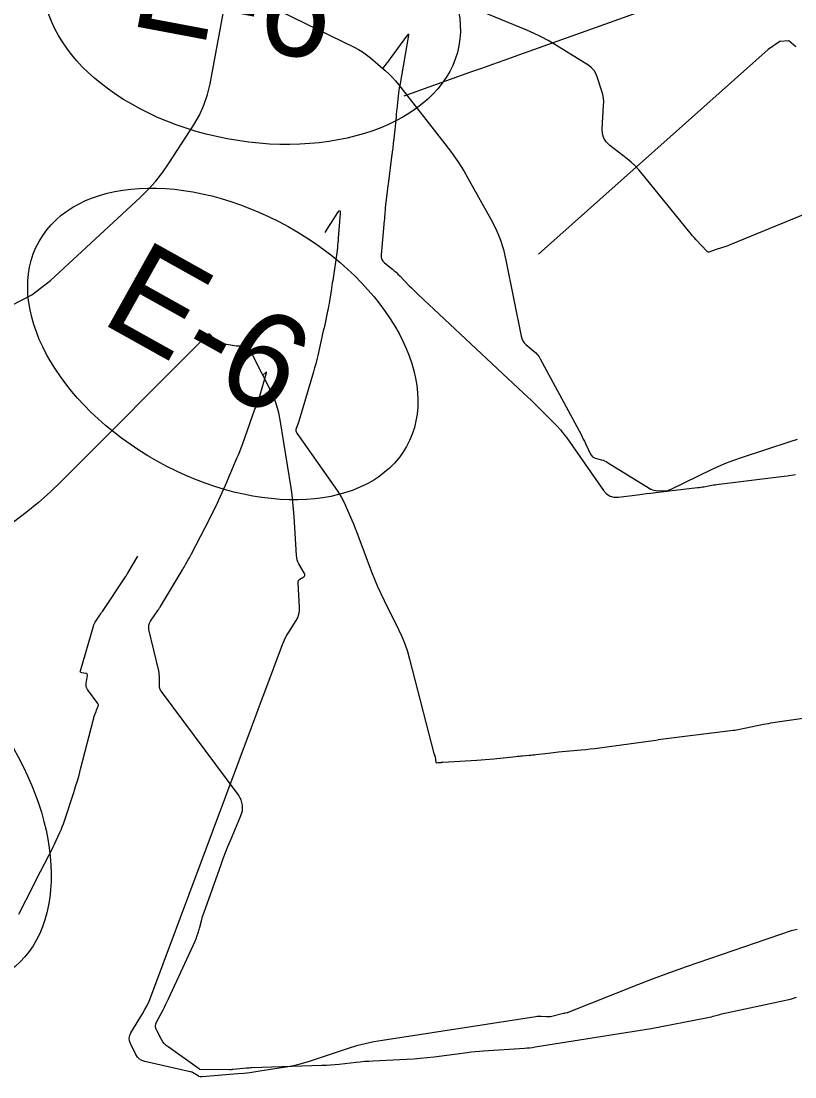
# Model space of a CAD drawing. Extents: x 1005228 to 1008882, y 1883389 to 1885754.
# Drawn here: x 1008004.6 to 1008055, y 1884412.1 to 1884480.9 of the extents above; entities that cross this region are included whole.
import ezdxf

# ---------------------------------------------------------------- set-up
doc = ezdxf.new("R2010")
doc.units = 0
for name, color, linetype in [('ATDIMS', 7, 'Continuous'), ('C-ANNO-NOTE', 7, 'Continuous'), ('R_Erosion', 7, 'Continuous'), ('TSOBSTACLE', 7, 'Continuous')]:
    doc.layers.add(name, color=color, linetype=linetype)

msp = doc.modelspace()

# ---------------------------------------------------------------- linework, layer by layer
at = {"layer": 'ATDIMS'}
for points in [[(1008024.395, 1884467.109), (1008024.638, 1884467.493), (1008024.679, 1884467.557), (1008024.719, 1884467.621), (1008024.76, 1884467.685), (1008024.8, 1884467.749), (1008025.223, 1884468.415), (1008025.295, 1884468.511), (1008025.343, 1884468.535), (1008025.367, 1884468.487), (1008025.367, 1884468.367), (1008025.245, 1884466.744), (1008025.24, 1884466.676), (1008025.234, 1884466.609), (1008025.229, 1884466.542), (1008025.222, 1884466.475), (1008025.198, 1884466.206), (1008025.191, 1884466.139), (1008025.184, 1884466.072), (1008025.175, 1884466.005), (1008025.166, 1884465.938), (1008024.883, 1884463.986), (1008024.858, 1884463.818), (1008024.832, 1884463.65), (1008024.806, 1884463.482), (1008024.78, 1884463.314), (1008024.672, 1884462.642), (1008024.644, 1884462.475), (1008024.614, 1884462.307), (1008024.582, 1884462.141), (1008024.547, 1884461.974), (1008024.36, 1884461.102), (1008024.317, 1884460.901), (1008024.272, 1884460.701), (1008024.228, 1884460.5), (1008024.182, 1884460.3), (1008023.907, 1884459.096), (1008023.844, 1884458.829), (1008023.776, 1884458.563), (1008023.705, 1884458.299), (1008023.629, 1884458.035), (1008022.765, 1884455.11), (1008022.758, 1884455.084), (1008022.75, 1884455.058), (1008022.743, 1884455.032), (1008022.735, 1884455.007), (1008022.706, 1884454.904), (1008022.698, 1884454.878), (1008022.69, 1884454.852), (1008022.681, 1884454.827), (1008022.672, 1884454.802), (1008022.508, 1884454.353), (1008022.488, 1884454.271), (1008022.488, 1884454.192), (1008022.508, 1884454.115), (1008022.549, 1884454.041), (1008025.174, 1884450.298), (1008025.322, 1884450.075), (1008025.458, 1884449.845), (1008025.583, 1884449.609), (1008025.695, 1884449.367), (1008026.122, 1884448.383), (1008026.228, 1884448.136), (1008026.33, 1884447.889), (1008026.429, 1884447.639), (1008026.525, 1884447.389), (1008027.417, 1884445.012), (1008027.603, 1884444.535), (1008027.802, 1884444.063), (1008028.012, 1884443.596), (1008028.234, 1884443.134), (1008029.162, 1884441.267), (1008029.38, 1884440.798), (1008029.573, 1884440.32), (1008029.741, 1884439.832), (1008029.883, 1884439.335), (1008031.47, 1884433.19), (1008031.476, 1884433.169), (1008031.482, 1884433.148), (1008031.489, 1884433.127), (1008031.497, 1884433.107), (1008031.528, 1884433.025), (1008031.535, 1884433.004), (1008031.541, 1884432.984), (1008031.546, 1884432.962), (1008031.55, 1884432.941), (1008031.596, 1884432.626), (1008031.602, 1884432.608), (1008031.612, 1884432.595), (1008031.627, 1884432.588), (1008031.646, 1884432.586), (1008031.732, 1884432.59), (1008031.754, 1884432.591), (1008031.776, 1884432.593), (1008031.797, 1884432.594), (1008031.819, 1884432.596), (1008031.943, 1884432.608), (1008031.97, 1884432.61), (1008031.998, 1884432.613), (1008032.026, 1884432.615), (1008032.054, 1884432.616), (1008034.265, 1884432.753), (1008034.541, 1884432.771), (1008034.817, 1884432.793), (1008035.093, 1884432.817), (1008035.369, 1884432.845), (1008036.806, 1884432.996), (1008036.914, 1884433.007), (1008037.022, 1884433.017), (1008037.131, 1884433.027), (1008037.239, 1884433.036), (1008037.672, 1884433.071), (1008037.781, 1884433.08), (1008037.889, 1884433.091), (1008037.997, 1884433.102), (1008038.105, 1884433.115), (1008038.905, 1884433.211), (1008039.074, 1884433.231), (1008039.244, 1884433.25), (1008039.413, 1884433.267), (1008039.583, 1884433.283), (1008041.049, 1884433.416), (1008041.35, 1884433.445), (1008041.651, 1884433.478), (1008041.951, 1884433.514), (1008042.25, 1884433.553), (1008046.075, 1884434.078)], [(1008057.004, 1884435.683), (1008053.526, 1884435.172), (1008053.377, 1884435.149), (1008053.227, 1884435.124), (1008053.079, 1884435.096), (1008052.93, 1884435.067), (1008051.381, 1884434.744), (1008051.271, 1884434.722), (1008051.161, 1884434.703), (1008051.05, 1884434.686), (1008050.939, 1884434.671), (1008046.075, 1884434.078)]]:
    msp.add_lwpolyline(points, dxfattribs=at)
at = {"layer": 'C-ANNO-NOTE'}
for points in [[(1008003.991, 1884462.374), (1008005.303, 1884463.038), (1008006.51, 1884463.973), (1008012.358, 1884469.391), (1008012.881, 1884469.906), (1008013.368, 1884470.451), (1008013.821, 1884471.025), (1008014.238, 1884471.629), (1008015.836, 1884474.104), (1008016.202, 1884474.736), (1008016.503, 1884475.394), (1008016.737, 1884476.079), (1008016.906, 1884476.79), (1008017.871, 1884481.95)], [(1008021.499, 1884481.502), (1008026.278, 1884479.172), (1008026.559, 1884479.024), (1008026.828, 1884478.859), (1008027.086, 1884478.677), (1008027.332, 1884478.478), (1008028.297, 1884477.649), (1008028.532, 1884477.436), (1008028.756, 1884477.213), (1008028.969, 1884476.978), (1008029.171, 1884476.733), (1008032.18, 1884472.884), (1008032.613, 1884472.308), (1008033.022, 1884471.717), (1008033.409, 1884471.11), (1008033.772, 1884470.489), (1008035.179, 1884467.971), (1008035.504, 1884467.332), (1008035.777, 1884466.673), (1008035.996, 1884465.995), (1008036.162, 1884465.297), (1008037.139, 1884460.348), (1008037.184, 1884460.192), (1008037.253, 1884460.049), (1008037.345, 1884459.921), (1008037.463, 1884459.807), (1008037.98, 1884459.382), (1008038.103, 1884459.271), (1008038.213, 1884459.149), (1008038.311, 1884459.017), (1008038.397, 1884458.875), (1008041.045, 1884453.944), (1008041.121, 1884453.8), (1008041.196, 1884453.654), (1008041.269, 1884453.508), (1008041.34, 1884453.361), (1008041.669, 1884452.668), (1008041.722, 1884452.58), (1008041.79, 1884452.509), (1008041.871, 1884452.456), (1008041.967, 1884452.419), (1008042.379, 1884452.309), (1008042.481, 1884452.277), (1008042.579, 1884452.239), (1008042.675, 1884452.193), (1008042.767, 1884452.14), (1008045.474, 1884450.449), (1008045.582, 1884450.39), (1008045.695, 1884450.347), (1008045.812, 1884450.319), (1008045.934, 1884450.307), (1008046.432, 1884450.287), (1008046.555, 1884450.289), (1008046.675, 1884450.306), (1008046.791, 1884450.339), (1008046.905, 1884450.386), (1008049.54, 1884451.67), (1008050.02, 1884451.894), (1008050.506, 1884452.101), (1008051, 1884452.291), (1008051.5, 1884452.465), (1008054.653, 1884453.497), (1008055.146, 1884453.659)], [(1008055.106, 1884421.728), (1008054.914, 1884421.688), (1008054.724, 1884421.631), (1008047.892, 1884419.293), (1008047.112, 1884419.021), (1008046.336, 1884418.739), (1008045.564, 1884418.448), (1008044.795, 1884418.147), (1008040.245, 1884416.335), (1008040.218, 1884416.325), (1008040.191, 1884416.316), (1008040.163, 1884416.308), (1008040.135, 1884416.301), (1008040.022, 1884416.274), (1008039.994, 1884416.267), (1008039.965, 1884416.26), (1008039.937, 1884416.254), (1008039.909, 1884416.247), (1008039.135, 1884416.06), (1008039.05, 1884416.043), (1008038.965, 1884416.033), (1008038.88, 1884416.03), (1008038.794, 1884416.033), (1008038.449, 1884416.059), (1008038.363, 1884416.064), (1008038.277, 1884416.063), (1008038.191, 1884416.057), (1008038.106, 1884416.046), (1008028.118, 1884414.507), (1008027.552, 1884414.408), (1008026.991, 1884414.286), (1008026.436, 1884414.14), (1008025.886, 1884413.971), (1008023.354, 1884413.136), (1008022.977, 1884413.02), (1008022.597, 1884412.919), (1008022.214, 1884412.834), (1008021.826, 1884412.764), (1008020.269, 1884412.514), (1008019.879, 1884412.455), (1008019.489, 1884412.403), (1008019.097, 1884412.359), (1008018.705, 1884412.323), (1008016.387, 1884412.13), (1008016.315, 1884412.129), (1008016.245, 1884412.14), (1008016.178, 1884412.162), (1008016.114, 1884412.195), (1008015.759, 1884412.415), (1008015.747, 1884412.421), (1008015.735, 1884412.427), (1008015.723, 1884412.432), (1008015.71, 1884412.435), (1008015.658, 1884412.449), (1008015.645, 1884412.452), (1008015.632, 1884412.455), (1008015.619, 1884412.458), (1008015.606, 1884412.461), (1008012.648, 1884413.135), (1008012.466, 1884413.197), (1008012.311, 1884413.291), (1008012.181, 1884413.42), (1008012.078, 1884413.581), (1008011.719, 1884414.296), (1008011.653, 1884414.473), (1008011.636, 1884414.649), (1008011.667, 1884414.823), (1008011.747, 1884414.995), (1008012.503, 1884416.241), (1008012.657, 1884416.508), (1008012.799, 1884416.782), (1008012.927, 1884417.063), (1008013.042, 1884417.35), (1008019.598, 1884434.88), (1008019.816, 1884435.462), (1008020.034, 1884436.043), (1008020.251, 1884436.625), (1008020.469, 1884437.206), (1008021.619, 1884440.27), (1008021.703, 1884440.48), (1008021.798, 1884440.684), (1008021.904, 1884440.884), (1008022.02, 1884441.078), (1008022.504, 1884441.844), (1008022.608, 1884442.04), (1008022.679, 1884442.244), (1008022.716, 1884442.458), (1008022.72, 1884442.68), (1008022.625, 1884444.305), (1008022.629, 1884444.375), (1008022.65, 1884444.437), (1008022.687, 1884444.489), (1008022.742, 1884444.533), (1008022.994, 1884444.691), (1008023.045, 1884444.734), (1008023.07, 1884444.783), (1008023.071, 1884444.838), (1008023.046, 1884444.899), (1008022.684, 1884445.531), (1008022.619, 1884445.661), (1008022.57, 1884445.795), (1008022.538, 1884445.934), (1008022.521, 1884446.077), (1008022.373, 1884448.613), (1008022.339, 1884449.083), (1008022.294, 1884449.553), (1008022.238, 1884450.021), (1008022.17, 1884450.488), (1008021.469, 1884454.905), (1008021.377, 1884455.371), (1008021.25, 1884455.826), (1008021.087, 1884456.269), (1008020.89, 1884456.702), (1008019.659, 1884459.147), (1008019.632, 1884459.206), (1008019.608, 1884459.265), (1008019.588, 1884459.326), (1008019.57, 1884459.387), (1008019.508, 1884459.637), (1008019.486, 1884459.691), (1008019.453, 1884459.727), (1008019.407, 1884459.746), (1008019.349, 1884459.748), (1008018.956, 1884459.703), (1008018.869, 1884459.696), (1008018.783, 1884459.695), (1008018.696, 1884459.7), (1008018.61, 1884459.71), (1008017.446, 1884459.889), (1008017.358, 1884459.911), (1008017.281, 1884459.951), (1008017.215, 1884460.007), (1008017.161, 1884460.08), (1008016.964, 1884460.404), (1008016.913, 1884460.467), (1008016.857, 1884460.492), (1008016.797, 1884460.481), (1008016.732, 1884460.432), (1008007.232, 1884450.916), (1008006.492, 1884450.203), (1008005.726, 1884449.521), (1008004.933, 1884448.87), (1008004.113, 1884448.25)]]:
    msp.add_lwpolyline(points, dxfattribs=at)
at = {"layer": 'R_Erosion'}
for centre, major_axis in [((1008019.637, 1884481.8), (13.46, -2.537)), ((1008017.727, 1884459.846), (11.958, -6.679)), ((1007995.859, 1884430.167), (7.993, -11.124))]:
    msp.add_ellipse(centre, major_axis=major_axis, ratio=0.638788, dxfattribs=at)
at = {"layer": 'TSOBSTACLE'}
for points in [[(1008053.568, 1884484.601), (1008036.738, 1884478.567), (1008036.016, 1884478.308), (1008035.293, 1884478.049), (1008034.571, 1884477.791), (1008033.848, 1884477.534), (1008029.511, 1884475.989)], [(1008056.82, 1884468.807), (1008050.798, 1884466.314), (1008050.699, 1884466.274), (1008050.599, 1884466.237), (1008050.498, 1884466.202), (1008050.396, 1884466.169), (1008049.898, 1884466.017), (1008049.84, 1884465.998), (1008049.782, 1884465.979), (1008049.725, 1884465.958), (1008049.668, 1884465.936), (1008049.441, 1884465.845), (1008049.386, 1884465.831), (1008049.335, 1884465.833), (1008049.287, 1884465.852), (1008049.244, 1884465.889), (1008048.546, 1884466.633), (1008048.417, 1884466.773), (1008048.29, 1884466.915), (1008048.167, 1884467.06), (1008048.046, 1884467.206), (1008045.036, 1884470.93), (1008044.81, 1884471.194), (1008044.569, 1884471.444), (1008044.314, 1884471.68), (1008044.046, 1884471.901), (1008042.918, 1884472.777), (1008042.69, 1884472.997), (1008042.533, 1884473.25), (1008042.446, 1884473.535), (1008042.43, 1884473.852), (1008042.517, 1884475.365), (1008042.52, 1884475.607), (1008042.501, 1884475.846), (1008042.461, 1884476.082), (1008042.399, 1884476.315), (1008042.106, 1884477.244), (1008042.016, 1884477.463), (1008041.893, 1884477.657), (1008041.736, 1884477.824), (1008041.546, 1884477.966), (1008039.345, 1884479.333), (1008038.905, 1884479.595), (1008038.455, 1884479.838), (1008037.995, 1884480.062), (1008037.526, 1884480.268), (1008032.82, 1884482.216)], [(1008028.119, 1884477.728), (1008028.432, 1884478.144), (1008028.484, 1884478.213), (1008028.536, 1884478.283), (1008028.587, 1884478.352), (1008028.639, 1884478.422), (1008029.78, 1884479.972), (1008029.784, 1884479.979), (1008029.789, 1884479.986), (1008029.793, 1884479.993), (1008029.796, 1884480), (1008029.809, 1884480.031), (1008029.812, 1884480.037), (1008029.815, 1884480.038), (1008029.816, 1884480.036), (1008029.817, 1884480.03), (1008029.82, 1884479.986), (1008029.82, 1884479.979), (1008029.82, 1884479.973), (1008029.815, 1884479.946), (1008029.245, 1884476.685), (1008029.217, 1884476.516), (1008029.192, 1884476.346), (1008029.169, 1884476.176), (1008029.149, 1884476.005), (1008029.076, 1884475.322), (1008029.057, 1884475.152), (1008029.039, 1884474.981), (1008029.021, 1884474.81), (1008029.004, 1884474.639), (1008028.857, 1884473.209), (1008028.825, 1884472.914), (1008028.792, 1884472.619), (1008028.757, 1884472.324), (1008028.719, 1884472.03), (1008028.51, 1884470.432), (1008028.49, 1884470.274), (1008028.469, 1884470.116), (1008028.449, 1884469.958), (1008028.43, 1884469.8), (1008028.336, 1884469.046), (1008028.325, 1884468.949), (1008028.314, 1884468.852), (1008028.305, 1884468.755), (1008028.297, 1884468.658), (1008028.268, 1884468.269), (1008028.26, 1884468.171), (1008028.253, 1884468.074), (1008028.244, 1884467.977), (1008028.236, 1884467.88), (1008028.031, 1884465.646), (1008028.033, 1884465.492), (1008028.072, 1884465.353), (1008028.146, 1884465.23), (1008028.255, 1884465.122), (1008028.764, 1884464.72), (1008028.889, 1884464.617), (1008029.011, 1884464.511), (1008029.129, 1884464.401), (1008029.244, 1884464.286), (1008029.87, 1884463.641), (1008030.013, 1884463.496), (1008030.157, 1884463.352), (1008030.303, 1884463.21), (1008030.451, 1884463.07), (1008037.306, 1884456.645), (1008037.552, 1884456.413), (1008037.796, 1884456.18), (1008038.039, 1884455.944), (1008038.28, 1884455.707), (1008039.243, 1884454.756), (1008039.478, 1884454.513), (1008039.701, 1884454.261), (1008039.912, 1884453.999), (1008040.112, 1884453.727), (1008042.517, 1884450.296), (1008042.709, 1884450.081), (1008042.934, 1884449.938), (1008043.19, 1884449.869), (1008043.479, 1884449.871), (1008044.729, 1884450.033), (1008045.018, 1884450.07), (1008045.308, 1884450.106), (1008045.597, 1884450.141), (1008045.887, 1884450.175), (1008048.629, 1884450.493), (1008048.733, 1884450.506), (1008048.837, 1884450.52), (1008048.941, 1884450.537), (1008049.045, 1884450.555), (1008049.458, 1884450.632), (1008049.562, 1884450.65), (1008049.665, 1884450.667), (1008049.769, 1884450.682), (1008049.874, 1884450.696), (1008053.9, 1884451.193), (1008054.455, 1884451.267), (1008055.007, 1884451.351)], [(1008055.035, 1884479.191), (1008054.581, 1884479.588), (1008053.979, 1884479.534), (1008053.231, 1884479.026), (1008038.282, 1884465.689)], [(1008016.219, 1884412.625), (1008016.212, 1884412.625), (1008016.21, 1884412.626), (1008014.162, 1884414.079), (1008014.035, 1884414.181), (1008013.922, 1884414.295), (1008013.824, 1884414.421), (1008013.74, 1884414.561), (1008013.434, 1884415.143), (1008013.377, 1884415.288), (1008013.358, 1884415.434), (1008013.377, 1884415.58), (1008013.434, 1884415.725), (1008013.839, 1884416.498), (1008013.931, 1884416.676), (1008014.021, 1884416.856), (1008014.108, 1884417.036), (1008014.193, 1884417.217), (1008015.922, 1884420.967), (1008015.954, 1884421.041), (1008015.985, 1884421.116), (1008016.013, 1884421.191), (1008016.04, 1884421.267), (1008016.14, 1884421.574), (1008016.165, 1884421.651), (1008016.188, 1884421.728), (1008016.21, 1884421.806), (1008016.231, 1884421.884), (1008016.354, 1884422.366), (1008016.383, 1884422.472), (1008016.414, 1884422.577), (1008016.447, 1884422.681), (1008016.483, 1884422.785), (1008017.614, 1884425.958), (1008017.759, 1884426.353), (1008017.909, 1884426.746), (1008018.066, 1884427.136), (1008018.228, 1884427.524), (1008018.891, 1884429.071), (1008019.004, 1884429.452), (1008019.014, 1884429.82), (1008018.919, 1884430.176), (1008018.72, 1884430.52), (1008013.744, 1884437.216), (1008013.683, 1884437.312), (1008013.64, 1884437.414), (1008013.614, 1884437.522), (1008013.605, 1884437.636), (1008013.607, 1884438.102), (1008013.604, 1884438.218), (1008013.595, 1884438.334), (1008013.578, 1884438.448), (1008013.555, 1884438.562), (1008012.923, 1884441.255), (1008012.904, 1884441.399), (1008012.914, 1884441.536), (1008012.954, 1884441.669), (1008013.024, 1884441.796), (1008013.502, 1884442.497), (1008013.517, 1884442.518), (1008013.531, 1884442.54), (1008013.546, 1884442.562), (1008013.56, 1884442.583), (1008013.618, 1884442.67), (1008013.633, 1884442.692), (1008013.647, 1884442.714), (1008013.661, 1884442.736), (1008013.674, 1884442.758), (1008015.104, 1884445.152), (1008015.154, 1884445.237), (1008015.205, 1884445.322), (1008015.255, 1884445.407), (1008015.305, 1884445.492), (1008015.504, 1884445.834), (1008015.554, 1884445.92), (1008015.602, 1884446.006), (1008015.649, 1884446.093), (1008015.695, 1884446.18), (1008016.56, 1884447.852), (1008016.639, 1884448.005), (1008016.718, 1884448.159), (1008016.796, 1884448.312), (1008016.873, 1884448.466), (1008017.184, 1884449.081), (1008017.26, 1884449.236), (1008017.335, 1884449.391), (1008017.408, 1884449.547), (1008017.478, 1884449.704), (1008017.894, 1884450.646), (1008017.986, 1884450.855), (1008018.078, 1884451.065), (1008018.168, 1884451.275), (1008018.259, 1884451.486), (1008018.652, 1884452.406), (1008018.746, 1884452.63), (1008018.837, 1884452.856), (1008018.924, 1884453.083), (1008019.007, 1884453.311), (1008019.824, 1884455.597), (1008019.852, 1884455.676), (1008019.88, 1884455.754), (1008019.909, 1884455.833), (1008019.937, 1884455.911), (1008020.052, 1884456.225), (1008020.08, 1884456.303), (1008020.107, 1884456.383), (1008020.132, 1884456.462), (1008020.156, 1884456.542), (1008020.562, 1884457.958), (1008020.569, 1884457.991), (1008020.564, 1884458.006), (1008020.548, 1884458.003), (1008020.522, 1884457.984), (1008020.33, 1884457.814)], [(1008004.458, 1884422.715), (1008005.377, 1884424.552), (1008005.496, 1884424.789), (1008005.617, 1884425.026), (1008005.739, 1884425.262), (1008005.861, 1884425.498), (1008006.41, 1884426.545), (1008006.505, 1884426.728), (1008006.597, 1884426.913), (1008006.687, 1884427.098), (1008006.775, 1884427.285), (1008007.12, 1884428.035), (1008007.204, 1884428.224), (1008007.282, 1884428.415), (1008007.355, 1884428.607), (1008007.422, 1884428.803), (1008008.029, 1884430.653), (1008008.148, 1884431.028), (1008008.261, 1884431.404), (1008008.369, 1884431.783), (1008008.47, 1884432.163), (1008009.309, 1884435.428), (1008009.325, 1884435.488), (1008009.343, 1884435.548), (1008009.362, 1884435.607), (1008009.382, 1884435.665), (1008009.475, 1884435.927), (1008009.491, 1884435.971), (1008009.508, 1884436.015), (1008009.526, 1884436.059), (1008009.544, 1884436.103), (1008009.618, 1884436.276), (1008009.631, 1884436.319), (1008009.632, 1884436.36), (1008009.621, 1884436.4), (1008009.599, 1884436.438), (1008008.928, 1884437.342), (1008008.872, 1884437.432), (1008008.838, 1884437.528), (1008008.824, 1884437.629), (1008008.83, 1884437.735), (1008008.911, 1884438.258), (1008008.912, 1884438.315), (1008008.894, 1884438.357), (1008008.858, 1884438.386), (1008008.803, 1884438.402), (1008008.548, 1884438.434), (1008008.494, 1884438.449), (1008008.461, 1884438.477), (1008008.448, 1884438.519), (1008008.456, 1884438.574), (1008009.302, 1884441.465), (1008009.332, 1884441.555), (1008009.369, 1884441.642), (1008009.412, 1884441.725), (1008009.463, 1884441.805), (1008009.677, 1884442.12), (1008009.731, 1884442.199), (1008009.784, 1884442.278), (1008009.837, 1884442.356), (1008009.89, 1884442.436), (1008011.39, 1884444.678), (1008011.406, 1884444.702), (1008011.421, 1884444.725), (1008011.436, 1884444.749), (1008011.45, 1884444.773), (1008011.508, 1884444.87), (1008011.522, 1884444.894), (1008011.537, 1884444.918), (1008011.551, 1884444.943), (1008011.565, 1884444.967), (1008012.188, 1884446.033)], [(1008045.605, 1884415.269), (1008049.198, 1884415.971), (1008049.309, 1884415.993), (1008049.419, 1884416.019), (1008049.529, 1884416.046), (1008049.638, 1884416.076), (1008050.074, 1884416.199), (1008050.184, 1884416.229), (1008050.294, 1884416.257), (1008050.404, 1884416.283), (1008050.514, 1884416.308), (1008054.273, 1884417.103), (1008054.474, 1884417.148), (1008054.674, 1884417.199), (1008054.872, 1884417.254), (1008055.068, 1884417.314)], [(1008016.219, 1884412.625), (1008018.169, 1884412.617), (1008018.228, 1884412.618), (1008018.286, 1884412.62), (1008018.344, 1884412.623), (1008018.402, 1884412.628), (1008019.268, 1884412.712), (1008019.355, 1884412.72), (1008019.441, 1884412.726), (1008019.527, 1884412.731), (1008019.614, 1884412.734), (1008024.181, 1884412.882), (1008024.459, 1884412.893), (1008024.737, 1884412.911), (1008025.015, 1884412.934), (1008025.292, 1884412.962), (1008026.399, 1884413.088), (1008026.676, 1884413.117), (1008026.953, 1884413.142), (1008027.231, 1884413.162), (1008027.509, 1884413.178), (1008029.685, 1884413.285), (1008030.135, 1884413.311), (1008030.585, 1884413.347), (1008031.033, 1884413.391), (1008031.48, 1884413.444), (1008033.63, 1884413.722), (1008033.897, 1884413.754), (1008034.164, 1884413.783), (1008034.432, 1884413.806), (1008034.7, 1884413.826), (1008037.366, 1884413.999), (1008037.542, 1884414.013), (1008037.717, 1884414.03), (1008037.892, 1884414.052), (1008038.066, 1884414.077), (1008045.605, 1884415.269)]]:
    msp.add_lwpolyline(points, dxfattribs=at)

# ---------------------------------------------------------------- texts
at = {"layer": 'R_Erosion'}
for rotation, p in [(349.32756, (1008011.521, 1884480.618)), (330.81503, (1008009.656, 1884461.302))]:
    msp.add_text('E-6', height=6.2498, rotation=rotation, dxfattribs=at).set_placement(p)

doc.saveas('drawing.dxf')
